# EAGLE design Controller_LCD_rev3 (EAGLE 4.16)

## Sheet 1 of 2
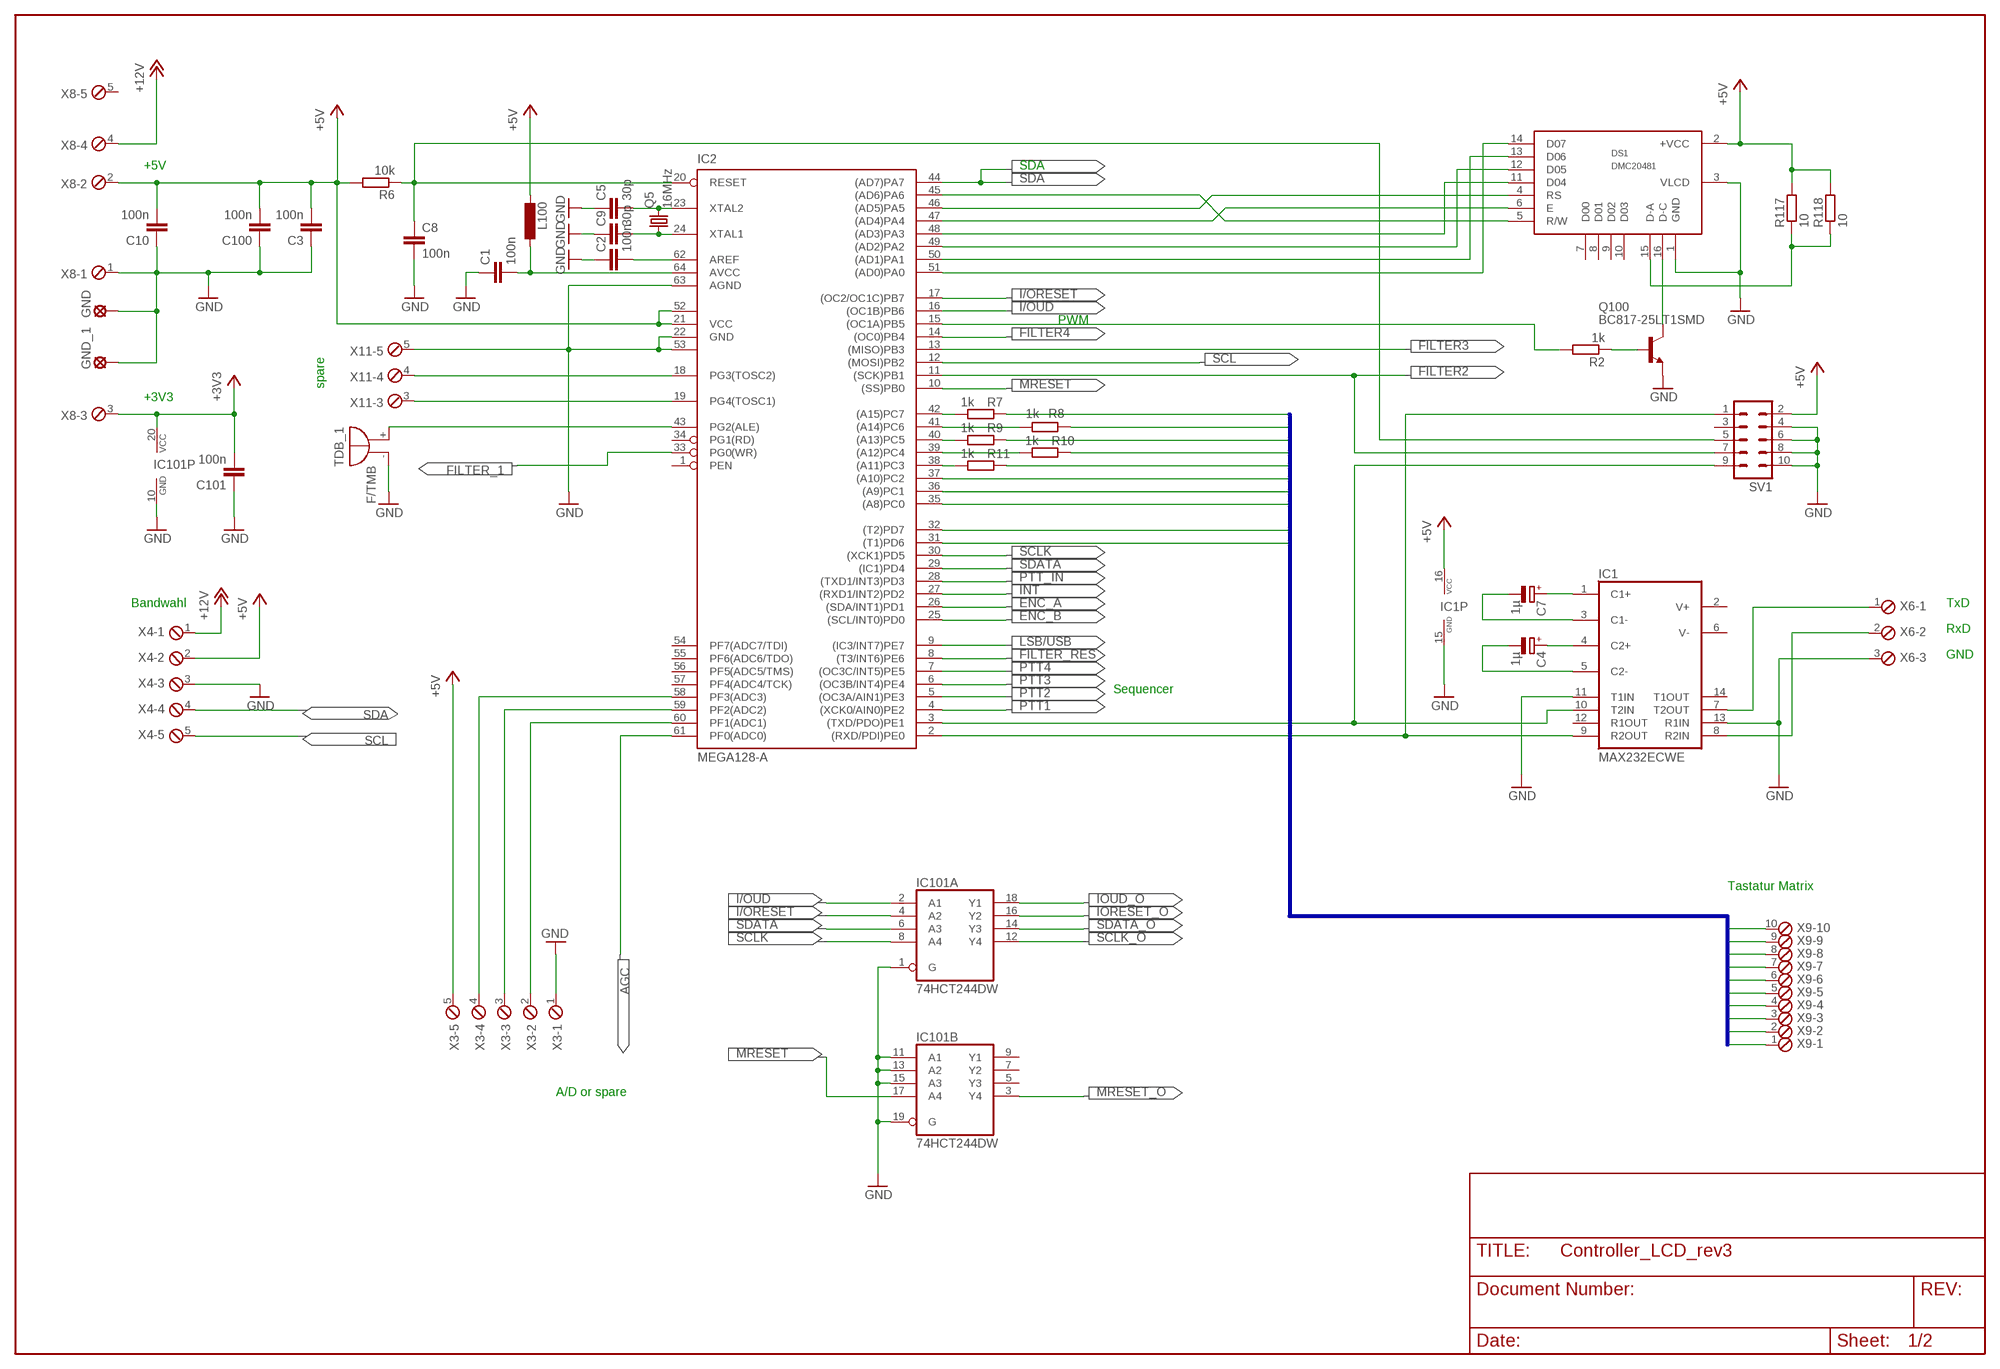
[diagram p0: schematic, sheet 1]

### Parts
C1  100n  C-EUC0805  [C0805]
C2  100n  C-EUC0805  [C0805]
C3  100n  C-EUC0805  [C0805]
C4  1µ  CPOL-EU153CLV-0505  [153CLV-0505]
C5  30p  C-EUC0805  [C0805]
C7  1µ  CPOL-EU153CLV-0505  [153CLV-0505]
C8  100n  C-EUC0805  [C0805]
C9  30p  C-EUC0805  [C0805]
C10  100n  C-EUC0805  [C0805]
C100  100n  C-EUC0805  [C0805]
C101  100n  C-EUC0805  [C0805]
DS1  DMC20481  [DM20481]
GND  LSP10  [LSP10]
GND_1  LSP10  [LSP10]
IC1  MAX232ECWE  [SO16L]
IC2  MEGA128-A  [TQFP64]
IC101  74HCT244DW  [SO20W]
L100  L-EUL1206  [L1206]
Q5  16MHz  CRYSTALHC49UP  [HC49UP]
Q100  BC817-25LT1SMD  [SOT23-BEC]
R2  1k  R-EU_M0805  [M0805]
R6  10k  R-EU_M0805  [M0805]
R7  1k  R-EU_M0805  [M0805]
R8  1k  R-EU_M0805  [M0805]
R9  1k  R-EU_M0805  [M0805]
R10  1k  R-EU_M0805  [M0805]
R11  1k  R-EU_M0805  [M0805]
R117  10  R-EU_M0805  [M0805]
R118  10  R-EU_M0805  [M0805]
SV1  ML10  [ML10]
TDB_1  F/TMB  [F/TMB]
X3  MPT5  [5POL254]
X4  MPT5  [5POL254]
X6  MPT3  [3POL254]
X8  MPT5  [5POL254]
X9  MPT10  [10POL254]
X11  MPT5  [5POL254]

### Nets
+3V3: C101.2 IC101.20(P:VCC) X8.3 ; also sheet 2
+5V: C3.2 C10.2 C100.2 DS1.2(+VCC) IC1.16(VCC) IC2.21(VCC) IC2.52(VCC1) L100.2 R6.2 R117.2 R118.2 SV1.2 X3.5 X4.2 X8.2 ; also sheet 2
+12V: X4.1 X8.4 ; also sheet 2
AGC: IC2.61(PF0(ADC0)) ; also sheet 2
COL1: IC2.37((A10)PC2) X9.5
COL2: IC2.36((A9)PC1) X9.4
COL3: IC2.35((A8)PC0) X9.3
COL4: IC2.32((T2)PD7) X9.2
COL5: IC2.31((T1)PD6) X9.1
D04: DS1.11(D04) IC2.48((AD3)PA3)
D05: DS1.12(D05) IC2.49((AD2)PA2)
D06: DS1.13(D06) IC2.50((AD1)PA1)
D07: DS1.14(D07) IC2.51((AD0)PA0)
E: DS1.6(E) IC2.47((AD4)PA4)
ENC_A: IC2.26((SDA/INT1)PD1) ; also sheet 2
ENC_B: IC2.25((SCL/INT0)PD0) ; also sheet 2
FILTER2: IC2.11((SCK)PB1) SV1.7 ; also sheet 2
FILTER3: IC2.13((MISO)PB3) ; also sheet 2
FILTER4: IC2.14((OC0)PB4) ; also sheet 2
FILTER_1: IC2.33(PG0(WR)) ; also sheet 2
FILTER_RES: IC2.8((T3/INT6)PE6) ; also sheet 2
GND: C1.1 C2.1 C3.1 C5.1 C8.2 C9.1 C10.1 C100.1 C101.1 DS1.1(GND) DS1.3(VLCD) GND.MP GND_1.MP IC1.11(T1IN) IC1.13(R1IN) IC1.15(GND) IC2.22(GND) IC2.53(GND1) IC2.63(AGND) IC101.1(A:G) IC101.10(P:GND) IC101.11(B:A1) IC101.13(B:A2) IC101.15(B:A3) IC101.19(B:G) Q100.E SV1.4 SV1.6 SV1.8 SV1.10 TDB_1.- X3.1 X4.3 X6.3 X8.1 X11.5 ; also sheet 2
I/ORESET: IC2.17((OC2/OC1C)PB7) IC101.4(A:A2)
I/OUD: IC2.16((OC1B)PB6) IC101.2(A:A1)
INT: IC2.27((RXD1/INT2)PD2) ; also sheet 2
IORESET_O: IC101.16(A:Y2) ; also sheet 2
IOUD_O: IC101.18(A:Y1) ; also sheet 2
LSB/USB: IC2.9((IC3/INT7)PE7) ; also sheet 2
MRESET: IC2.10((SS)PB0) IC101.17(B:A4)
MRESET_O: IC101.3(B:Y4) ; also sheet 2
N1: IC2.39((A12)PC4) R10.2
N2: IC2.41((A14)PC6) R8.2
N$1: C5.2 IC2.23(XTAL2) Q5.2
N$2: C9.2 IC2.24(XTAL1) Q5.1
N$8: DS1.15(D-A) R117.1 R118.1
N$9: Q100.B R2.1
N$13: IC2.15((OC1A)PB5) R2.2
N$14: IC1.9(R2OUT) IC2.2((RXD/PDI)PE0) SV1.1
N$15: IC1.10(T2IN) IC2.3((TXD/PDO)PE1) SV1.9
N$19: C7.+ IC1.1(C1+)
N$20: C7.- IC1.3(C1-)
N$21: C4.+ IC1.4(C2+)
N$22: C4.- IC1.5(C2-)
N$23: DS1.16(D-C) Q100.C
N$28: IC2.58(PF3(ADC3)) X3.4
N$29: IC2.59(PF2(ADC2)) X3.3
N$30: IC2.60(PF1(ADC1)) X3.2
N$38: IC2.38((A11)PC3) R11.2
N$39: IC2.40((A13)PC5) R9.2
N$40: IC2.42((A15)PC7) R7.2
N$79: IC2.43(PG2(ALE)) TDB_1.+
N$80: IC2.18(PG3(TOSC2)) X11.4
N$81: IC2.19(PG4(TOSC1)) X11.3
N$83: C2.2 IC2.62(AREF)
N$84: C1.2 IC2.64(AVCC) L100.1
PTT1: IC2.4((XCK0/AIN0)PE2) ; also sheet 2
PTT2: IC2.5((OC3A/AIN1)PE3) ; also sheet 2
PTT3: IC2.6((OC3B/INT4)PE4) ; also sheet 2
PTT4: IC2.7((OC3C/INT5)PE5) ; also sheet 2
PTT_IN: IC2.28((TXD1/INT3)PD3) ; also sheet 2
R/W: DS1.5(R/W) IC2.45((AD6)PA6)
RESET: C8.1 IC2.20(RESET) R6.1 SV1.5
ROW1: R7.1 X9.10
ROW2: R8.1 X9.9
ROW3: R9.1 X9.8
ROW4: R10.1 X9.7
ROW5: R11.1 X9.6
RS: DS1.4(RS) IC2.46((AD5)PA5)
RXD: IC1.8(R2IN) X6.2
SCL: IC2.12((MOSI)PB2) X4.5 ; also sheet 2
SCLK: IC2.30((XCK1)PD5) IC101.8(A:A4)
SCLK_O: IC101.12(A:Y4) ; also sheet 2
SDA: IC2.44((AD7)PA7) X4.4 ; also sheet 2
SDATA: IC2.29((IC1)PD4) IC101.6(A:A3)
SDATA_O: IC101.14(A:Y3) ; also sheet 2
TXD: IC1.7(T2OUT) X6.1
Unconnected: DS1.7(D00) DS1.8(D01) DS1.9(D02) DS1.10(D03) IC1.2(V+) IC1.6(V-) IC1.12(R1OUT) IC1.14(T1OUT) IC2.1(PEN) IC2.34(PG1(RD)) IC2.54(PF7(ADC7/TDI)) IC2.55(PF6(ADC6/TDO)) IC2.56(PF5(ADC5/TMS)) IC2.57(PF4(ADC4/TCK)) IC101.5(B:Y3) IC101.7(B:Y2) IC101.9(B:Y1) SV1.3 X8.5 X11.1 X11.2

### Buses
KEY

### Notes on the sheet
- +5V | SDA
- PWM
- spare
- +3V3
- Bandwahl | TxD
- RxD
- GND
- Sequencer
- Tastatur Matrix
- A/D or spare

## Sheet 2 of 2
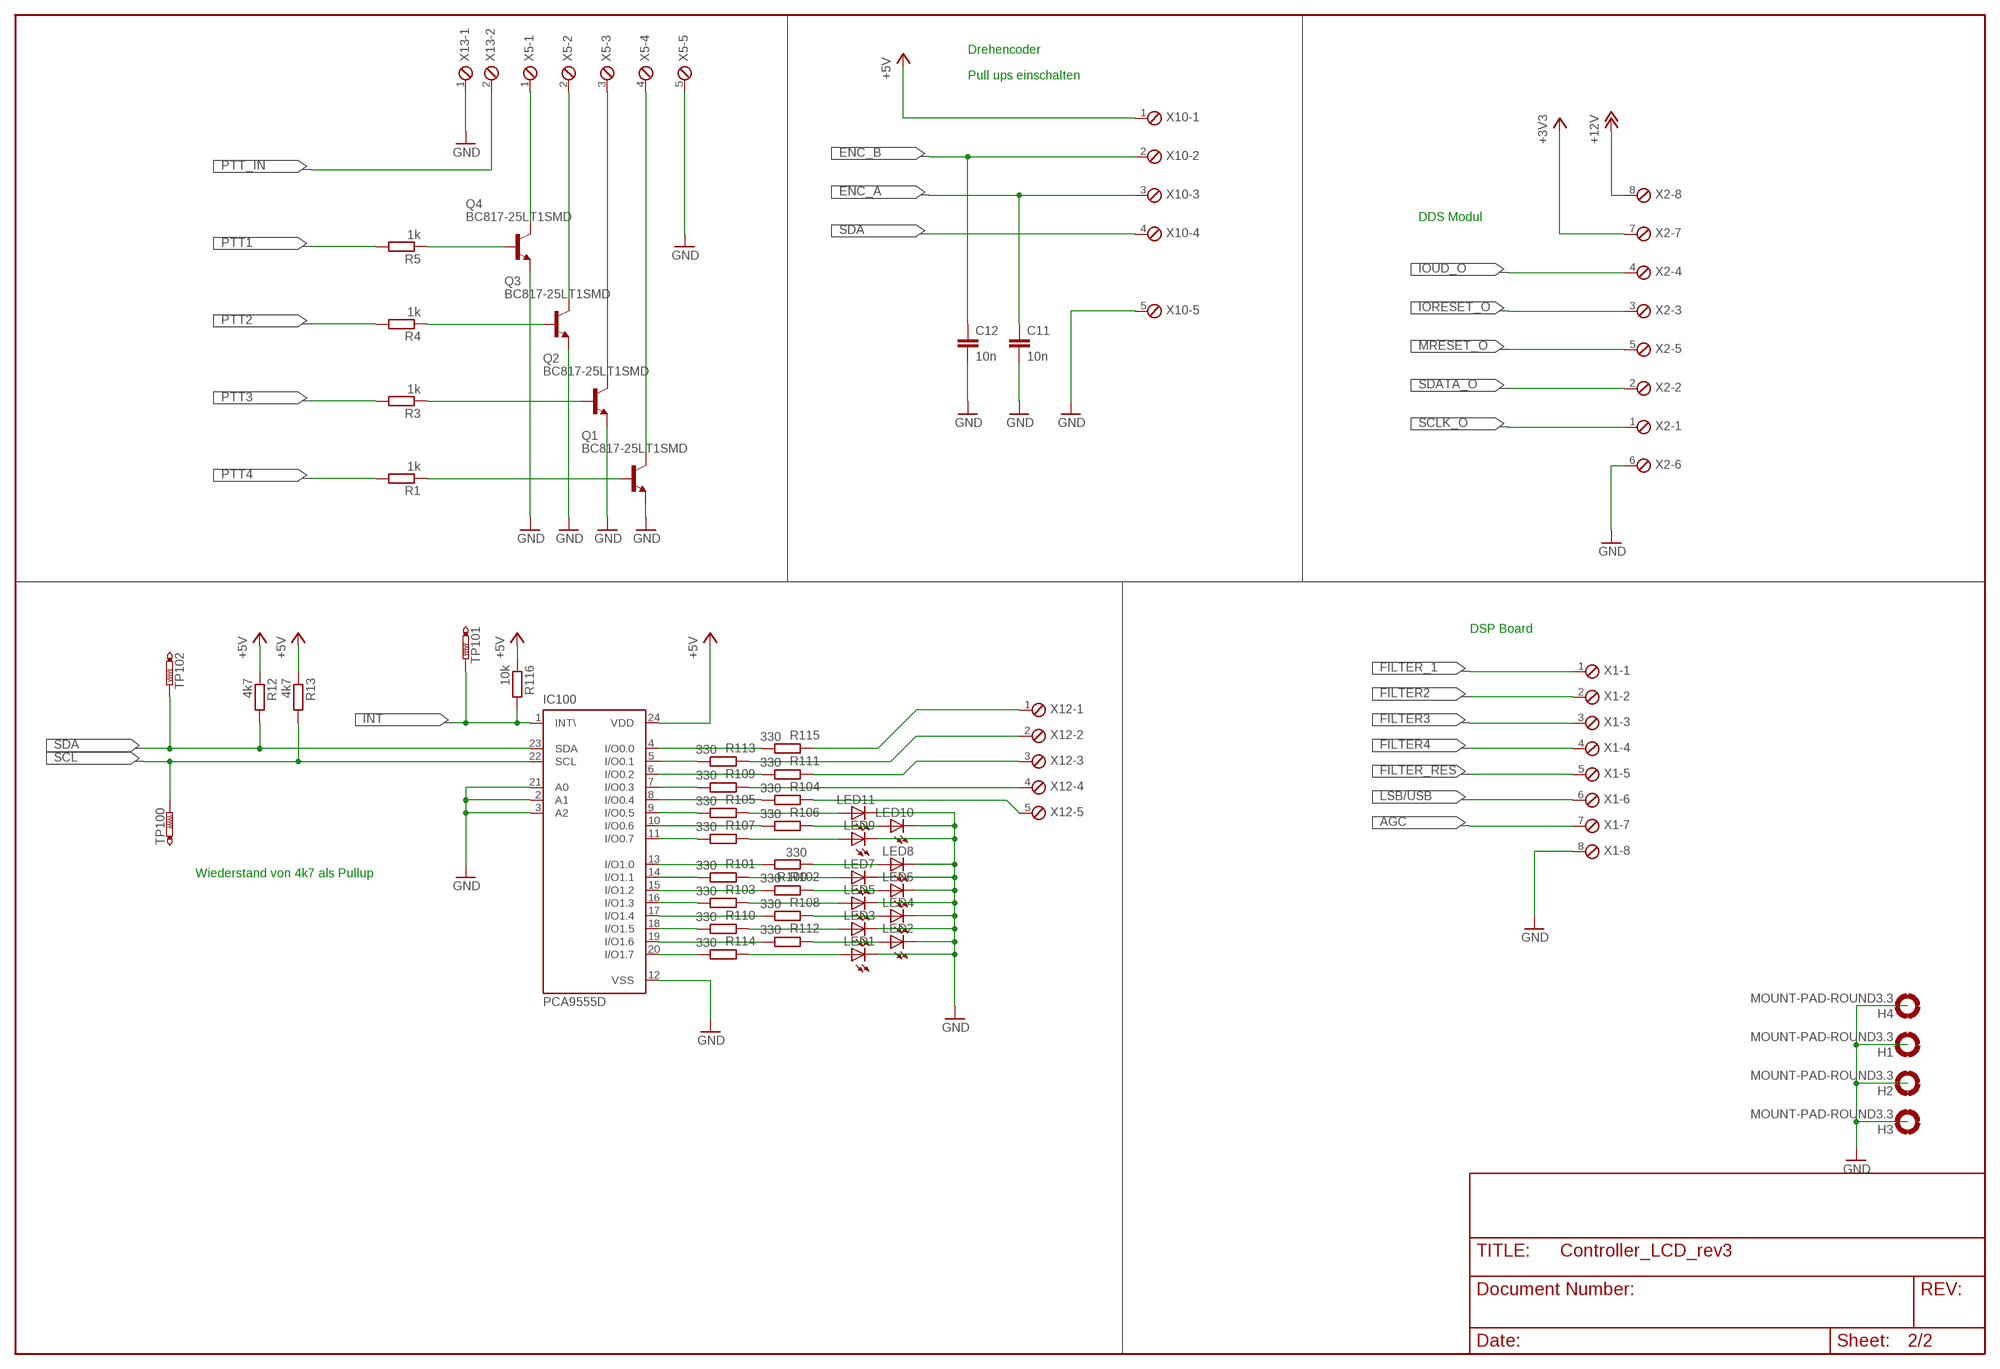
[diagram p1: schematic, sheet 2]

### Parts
C11  10n  C-EUC0805K  [C0805K]
C12  10n  C-EUC0805K  [C0805K]
H1  MOUNT-PAD-ROUND3.3  [3,3-PAD]
H2  MOUNT-PAD-ROUND3.3  [3,3-PAD]
H3  MOUNT-PAD-ROUND3.3  [3,3-PAD]
H4  MOUNT-PAD-ROUND3.3  [3,3-PAD]
IC100  PCA9555D  [SO24]
LED1  LED5MM  [LED5MM]
LED2  LED5MM  [LED5MM]
LED3  LED5MM  [LED5MM]
LED4  LED5MM  [LED5MM]
LED5  LED5MM  [LED5MM]
LED6  LED5MM  [LED5MM]
LED7  LED5MM  [LED5MM]
LED8  LED5MM  [LED5MM]
LED9  LED5MM  [LED5MM]
LED10  LED5MM  [LED5MM]
LED11  LED5MM  [LED5MM]
Q1  BC817-25LT1SMD  [SOT23-BEC]
Q2  BC817-25LT1SMD  [SOT23-BEC]
Q3  BC817-25LT1SMD  [SOT23-BEC]
Q4  BC817-25LT1SMD  [SOT23-BEC]
R1  1k  R-EU_M0805  [M0805]
R3  1k  R-EU_M0805  [M0805]
R4  1k  R-EU_M0805  [M0805]
R5  1k  R-EU_M0805  [M0805]
R12  4k7  R-EU_M0805  [M0805]
R13  4k7  R-EU_M0805  [M0805]
R100  330  R-EU_M0805  [M0805]
R101  330  R-EU_M0805  [M0805]
R102  330  R-EU_M0805  [M0805]
R103  330  R-EU_M0805  [M0805]
R104  330  R-EU_M0805  [M0805]
R105  330  R-EU_M0805  [M0805]
R106  330  R-EU_M0805  [M0805]
R107  330  R-EU_M0805  [M0805]
R108  330  R-EU_M0805  [M0805]
R109  330  R-EU_M0805  [M0805]
R110  330  R-EU_M0805  [M0805]
R111  330  R-EU_M0805  [M0805]
R112  330  R-EU_M0805  [M0805]
R113  330  R-EU_M0805  [M0805]
R114  330  R-EU_M0805  [M0805]
R115  330  R-EU_M0805  [M0805]
R116  10k  R-EU_M0805  [M0805]
TP100  PTR1B2,54  [B2,54]
TP101  PTR1B2,54  [B2,54]
TP102  PTR1B2,54  [B2,54]
X1  MPT8  [8POL254]
X2  MPT8  [8POL254]
X5  MPT5  [5POL254]
X10  MPT5  [5POL254]
X12  MPT5  [5POL254]
X13  MPT2  [2POL254]

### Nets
+3V3: X2.7 ; also sheet 1
+5V: IC100.24(VDD) R12.1 R13.1 R116.1 X10.1 ; also sheet 1
+12V: X2.8 ; also sheet 1
AGC: X1.7 ; also sheet 1
ENC_A: C11.1 X10.3 ; also sheet 1
ENC_B: C12.1 X10.2 ; also sheet 1
FILTER2: X1.2 ; also sheet 1
FILTER3: X1.3 ; also sheet 1
FILTER4: X1.4 ; also sheet 1
FILTER_1: X1.1 ; also sheet 1
FILTER_RES: X1.5 ; also sheet 1
GND: C11.2 C12.2 H1.B3,3(MOUNT) H2.B3,3(MOUNT) H3.B3,3(MOUNT) H4.B3,3(MOUNT) IC100.2(A1) IC100.3(A2) IC100.12(VSS) IC100.21(A0) LED1.K(C) LED2.K(C) LED3.K(C) LED4.K(C) LED5.K(C) LED6.K(C) LED7.K(C) LED8.K(C) LED9.K(C) LED10.K(C) LED11.K(C) Q1.E Q2.E Q3.E Q4.E X1.8 X2.6 X5.5 X10.5 X13.1 ; also sheet 1
INT: IC100.1(INT\) R116.2 TP101.PP(TP) ; also sheet 1
IORESET_O: X2.3 ; also sheet 1
IOUD_O: X2.4 ; also sheet 1
LSB/USB: X1.6 ; also sheet 1
MRESET_O: X2.5 ; also sheet 1
N$3: Q4.B R5.1
N$12: IC100.4(I/O0.0) R115.2
N$17: IC100.5(I/O0.1) R113.2
N$18: IC100.6(I/O0.2) R111.2
N$31: Q3.B R4.1
N$32: Q2.B R3.1
N$33: Q1.B R1.1
N$34: Q4.C X5.1
N$35: Q3.C X5.2
N$36: Q2.C X5.3
N$37: Q1.C X5.4
N$41: IC100.7(I/O0.3) R109.2
N$42: IC100.8(I/O0.4) R104.2
N$43: IC100.9(I/O0.5) R105.2
N$44: IC100.10(I/O0.6) R106.2
N$45: IC100.11(I/O0.7) R107.2
N$46: R115.1 X12.1
N$47: R113.1 X12.2
N$48: R109.1 X12.4
N$49: R111.1 X12.3
N$50: R104.1 X12.5
N$51: LED11.A R105.1
N$52: LED10.A R106.1
N$53: LED9.A R107.1
N$54: IC100.20(I/O1.7) R114.2
N$55: IC100.19(I/O1.6) R112.2
N$56: IC100.18(I/O1.5) R110.2
N$57: IC100.17(I/O1.4) R108.2
N$58: IC100.16(I/O1.3) R103.2
N$59: IC100.15(I/O1.2) R102.2
N$60: IC100.14(I/O1.1) R101.2
N$61: IC100.13(I/O1.0) R100.2
N$62: LED8.A R100.1
N$63: LED7.A R101.1
N$64: LED5.A R103.1
N$65: LED6.A R102.1
N$66: LED4.A R108.1
N$67: LED3.A R110.1
N$68: LED2.A R112.1
N$69: LED1.A R114.1
PTT1: R5.2 ; also sheet 1
PTT2: R4.2 ; also sheet 1
PTT3: R3.2 ; also sheet 1
PTT4: R1.2 ; also sheet 1
PTT_IN: X13.2 ; also sheet 1
SCL: IC100.22(SCL) R13.2 TP100.PP(TP) ; also sheet 1
SCLK_O: X2.1 ; also sheet 1
SDA: IC100.23(SDA) R12.2 TP102.PP(TP) X10.4 ; also sheet 1
SDATA_O: X2.2 ; also sheet 1

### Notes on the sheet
- Drehencoder
- Pull ups einschalten
- DDS Modul
- DSP Board
- Wiederstand von 4k7 als Pullup

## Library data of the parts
C1-C3 C5 C8-C12 C100 C101 = rcl:C-EU: CAPACITOR, European symbol
C4 C7 = rcl:CPOL-EU: POLARIZED CAPACITOR, European symbol
DS1 = abi-lcd:DMC20481
GND GND_1 = solpad:LSP10: SOLDER PAD
H1-H4 = holes:MOUNT-PAD-ROUND: MOUNTING PAD, round
IC1 = maxim:MAX232ECWE: RS232 TRANSEIVER
IC2 = atmel:MEGA128: MICROCONTROLLER 128 Kbytes FLASH 4 Kbytes SRAM 4 Kbytes EEPROM DUAL USART 8-channel 10 bit ADC Source: avr.lbr
IC100 = micro-philips:PCA9555: 16-bit I2C and SMBus I/O port with interrupt Source: PCA9555_5.pdf
IC101 = 74xx-eu:74*244: Octal BUFFER and LINE DRIVER, 3-state
L100 = rcl:L-EU: INDUCTOR, European symbol
LED1-LED11 = led:LED: LED
Q1-Q4 Q100 = transistor-npn:BC817*: NPN Transistor
Q5 = crystal:CRYSTAL: CRYSTAL
R1-R13 R100-R118 = rcl:R-EU_: RESISTOR, European symbol
SV1 = con-harting-ml:ML10: HARTING
TDB_1 = buzzer:F/TMB: BUZZER
TP100-TP102 = testpad:PTR1: TEST PIN
X1 X2 = con-phoenix-254:MPT8: PHOENIX CONNECTOR
X3-X5 X8 X10-X12 = con-phoenix-254:MPT5: PHOENIX CONNECTOR
X6 = con-phoenix-254:MPT3: PHOENIX CONNECTOR
X9 = con-phoenix-254:MPT10: PHOENIX CONNECTOR
X13 = con-phoenix-254:MPT2: PHOENIX CONNECTOR

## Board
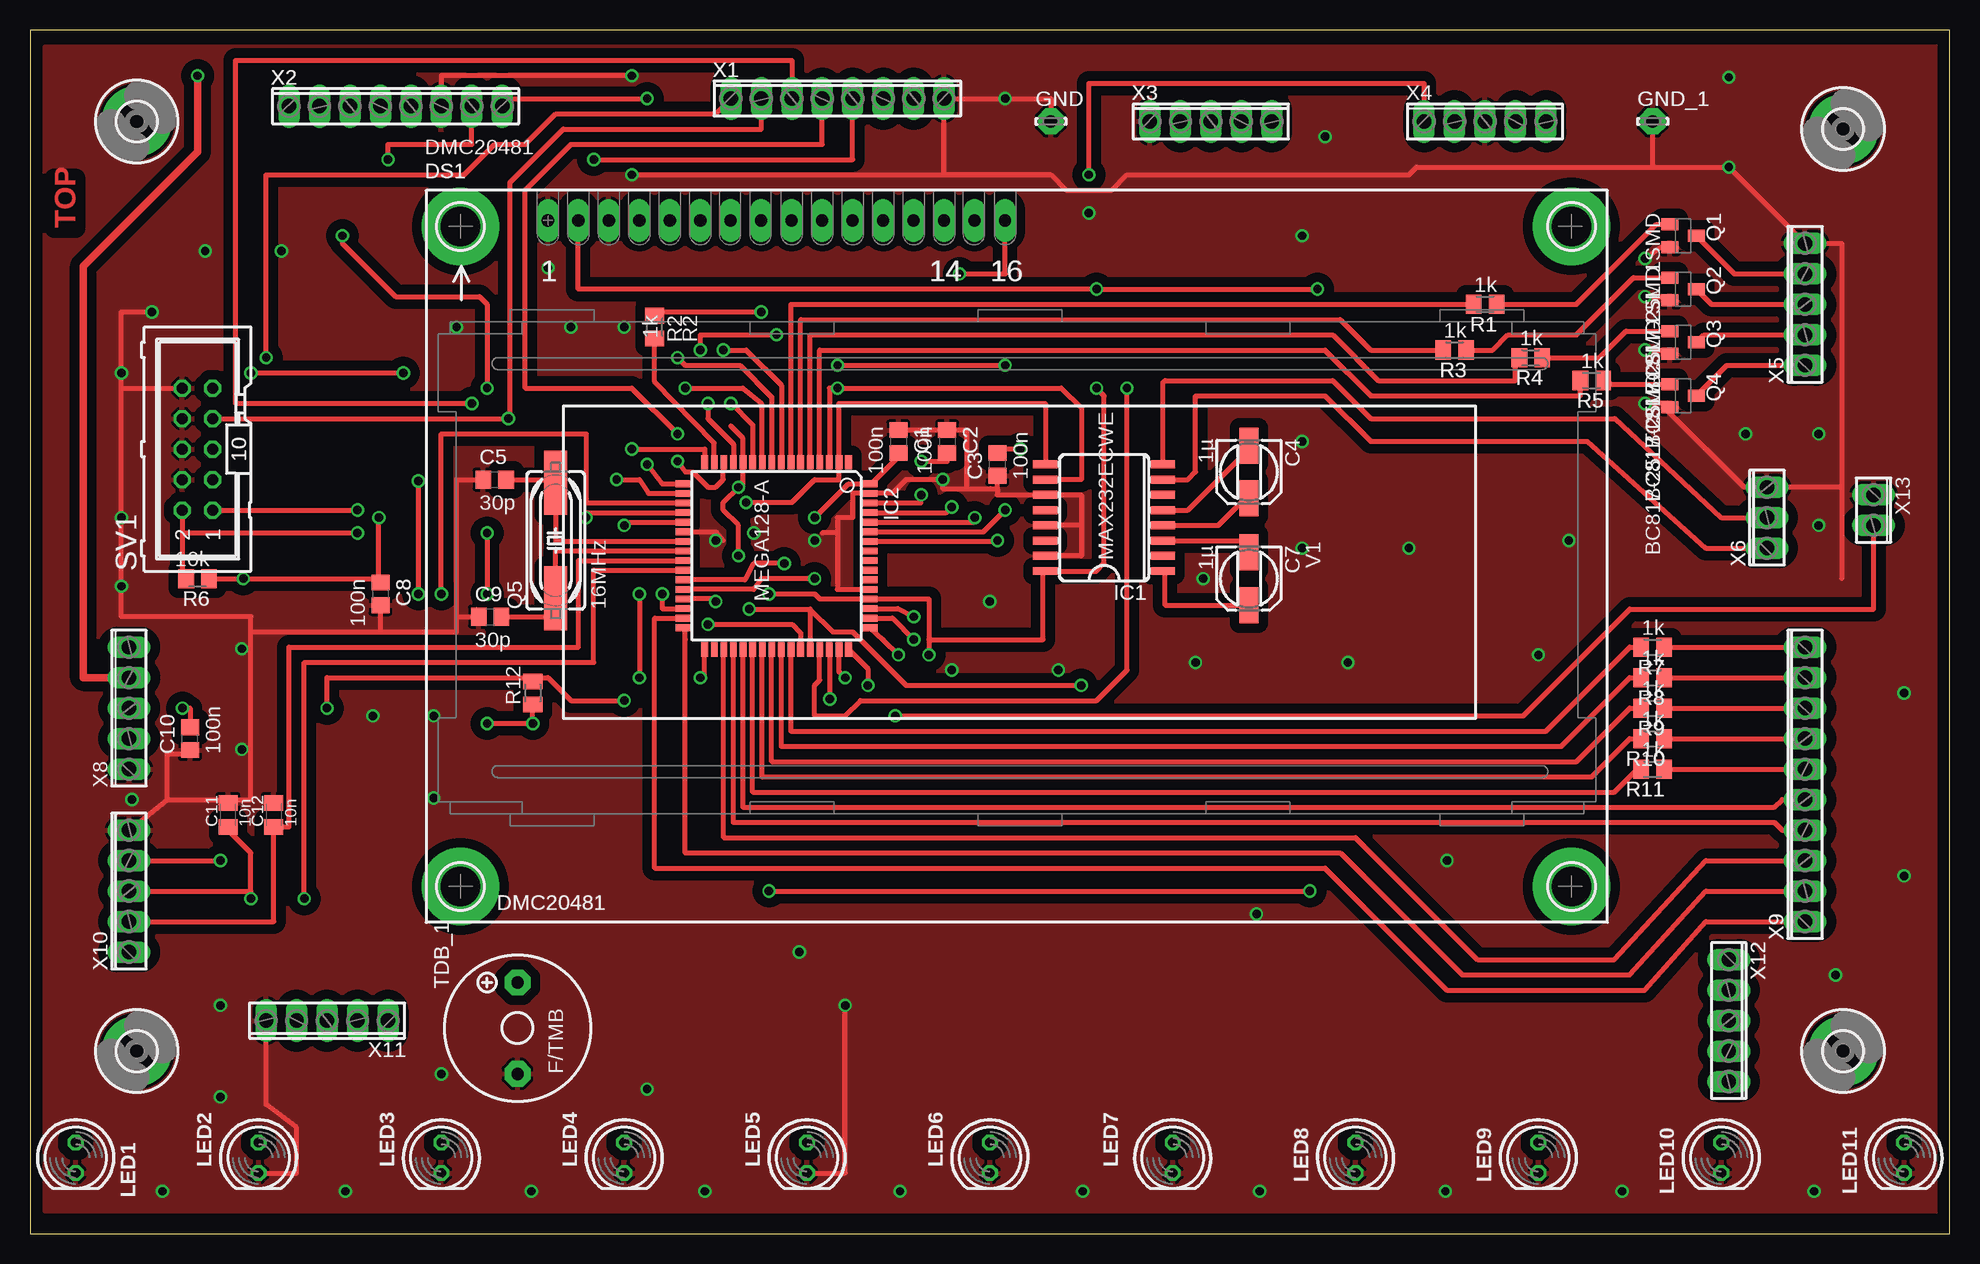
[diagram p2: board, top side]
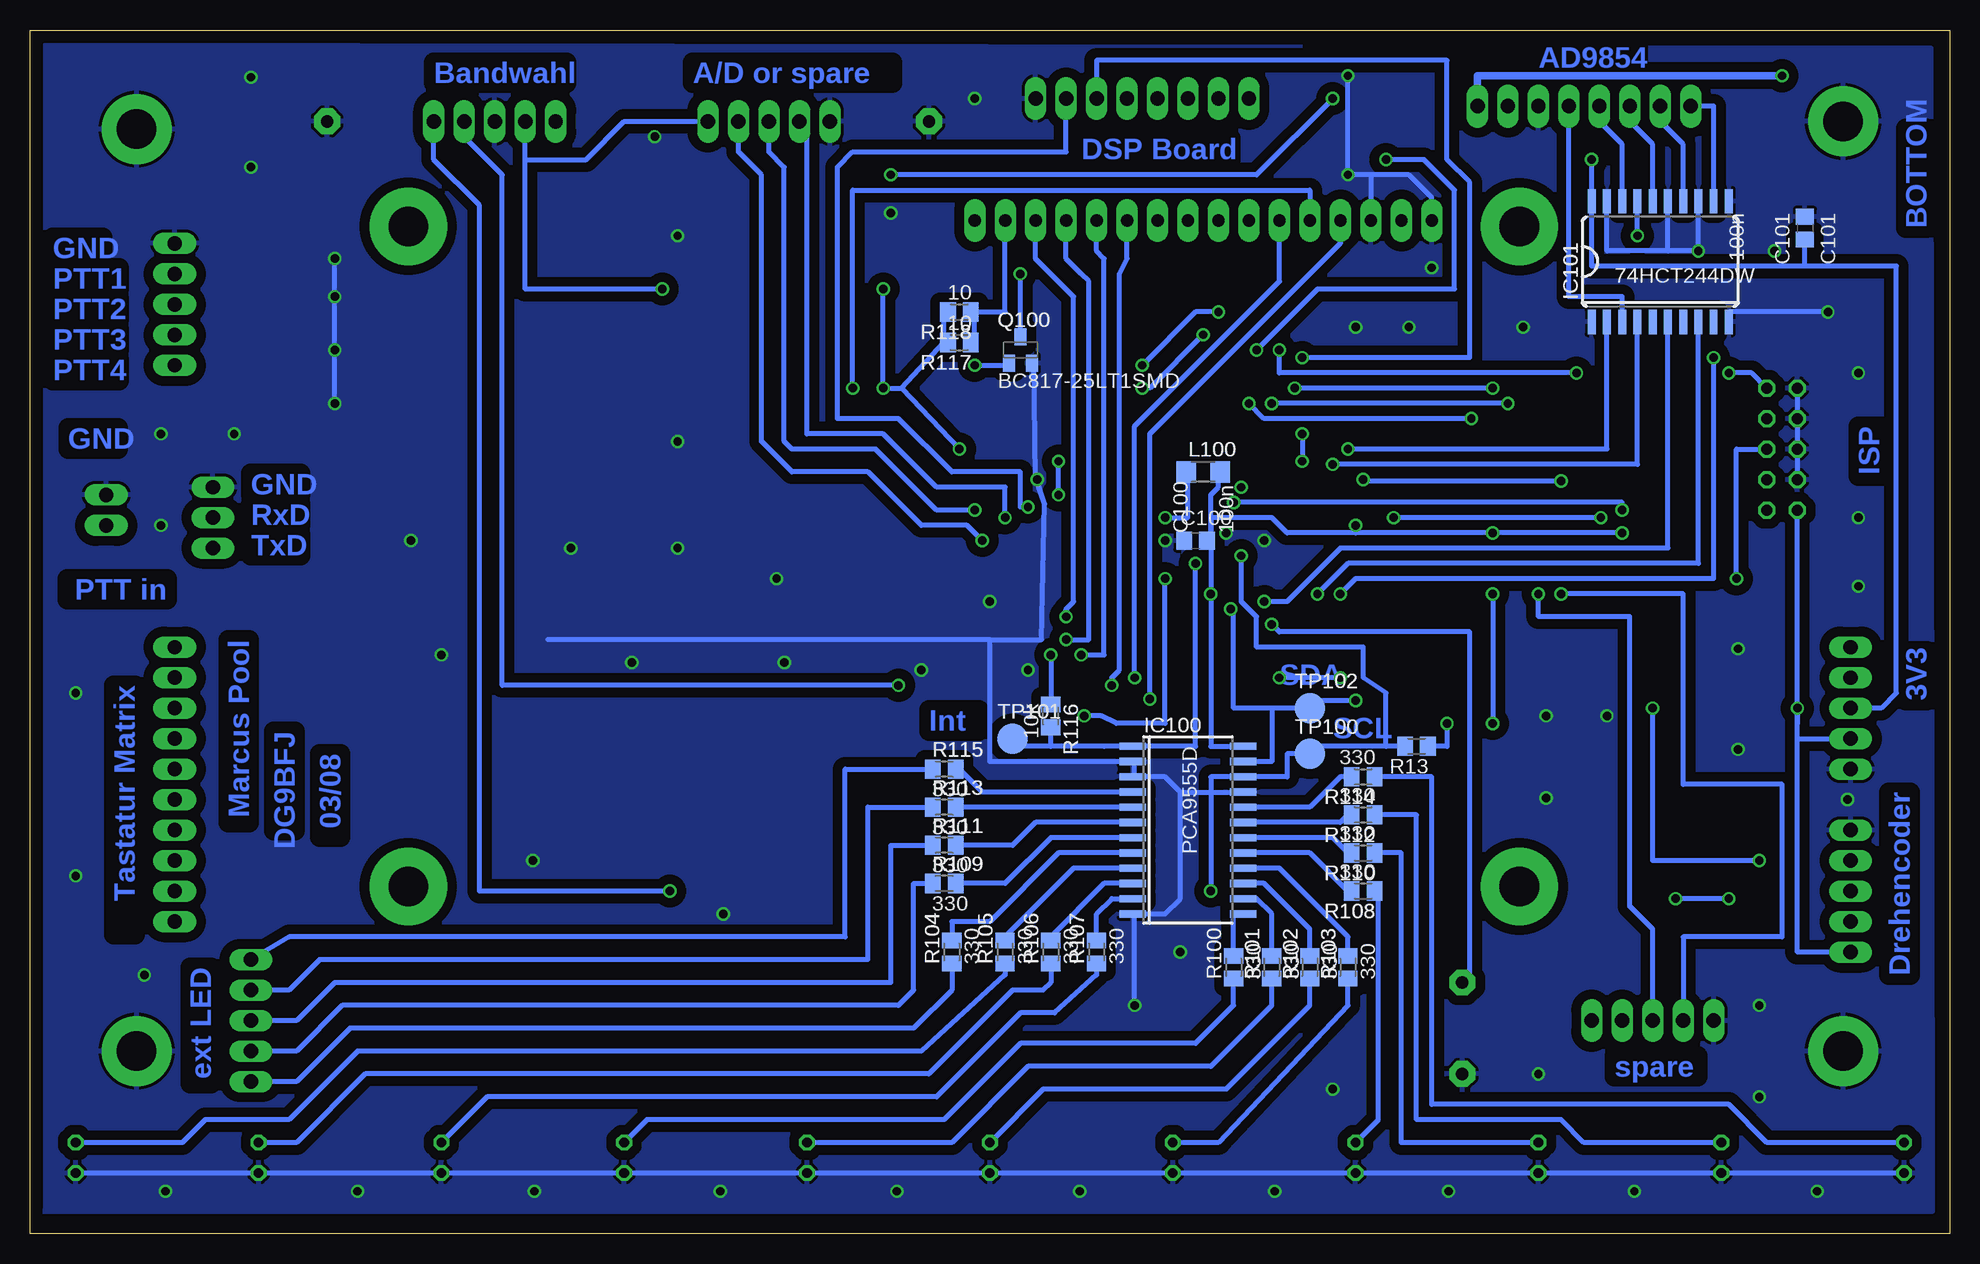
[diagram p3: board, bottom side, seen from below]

Size 160.02 x 100.33 mm. Coordinates in mm from the lower left corner, seen from the top.
Outline: 0,0 160.02,0 160.02,100.33 0,100.33 0,0
Copper layers (1*16): Top 0.035mm / dielectric 1.5mm / Bottom 0.035mm
Design rules "Bilex DRU": minimum track width 10mil, minimum drill 24mil, track to track 10mil, track to pad 10mil, pad to pad 10mil, via to via 10mil, smd to smd 10mil, copper to edge 40mil, drill to drill 8mil, minimum pad ring 10mil, minimum via ring 8mil, stop-mask expansion 4mil, vias tented up to drill 0mil, thermal gap 10mil

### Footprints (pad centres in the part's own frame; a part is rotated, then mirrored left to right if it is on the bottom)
C0805 = smd 1.3 x 1.5: 1 -0.95,0; 2 0.95,0
153CLV-0505 = smd 3 x 1.6: + 2.2,0; - -2.2,0
C0805K = smd 1.3 x 1.6: 1 -1,0; 2 1,0
DM20481 = drill 1.016 pad 1.778 long: 1 -39.383,29.21; 2 -36.843,29.21; 3 -34.303,29.21; 4 -31.763,29.21; 5 -29.223,29.21; 6 -26.683,29.21; 7 -24.143,29.21; 8 -21.603,29.21; 9 -19.063,29.21; 10 -16.523,29.21; 11 -13.983,29.21; 12 -11.443,29.21; 13 -8.903,29.21; 14 -6.363,29.21; 15 -3.823,29.21; 16 -1.283,29.21 | drill 3.3 pad 6.452: P$1 -46.672,-26.289; P$2 45.936,-26.289; P$3 45.936,28.715; P$4 -46.672,28.702
LSP10 = drill 1.016 pad 2.159 octagon: MP 0,0
3,3-PAD = drill 3.3 pad 5.842: B3,3 0,0
SO16L = smd 0.66 x 2.032: 1 -4.445,-4.902; 2 -3.175,-4.902; 3 -1.905,-4.902; 4 -0.635,-4.902; 5 0.635,-4.902; 6 1.905,-4.902; 7 3.175,-4.902; 8 4.445,-4.902; 9 4.445,4.902; 10 3.175,4.902; 11 1.905,4.902; 12 0.635,4.902; 13 -0.635,4.902; 14 -1.905,4.902; 15 -3.175,4.902; 16 -4.445,4.902
TQFP64 = smd 1.194 x 0.559: 1 -7.8,6; 2 -7.8,5.2; 3 -7.8,4.4; 4 -7.8,3.6; 5 -7.8,2.8; 6 -7.8,2; 7 -7.8,1.2; 8 -7.8,0.4; 9 -7.8,-0.4; 10 -7.8,-1.2; 11 -7.8,-2; 12 -7.8,-2.8; 13 -7.8,-3.6; 14 -7.8,-4.4; 15 -7.8,-5.2; 16 -7.8,-6; 33 7.8,-6; 34 7.8,-5.2; 35 7.8,-4.4; 36 7.8,-3.6; 37 7.8,-2.8; 38 7.8,-2; 39 7.8,-1.2; 40 7.8,-0.4; 41 7.8,0.4; 42 7.8,1.2; 43 7.8,2; 44 7.8,2.8; 45 7.8,3.6; 46 7.8,4.4; 47 7.8,5.2; 48 7.8,6 | smd 0.559 x 1.194: 17 -6,-7.8; 18 -5.2,-7.8; 19 -4.4,-7.8; 20 -3.6,-7.8; 21 -2.8,-7.8; 22 -2,-7.8; 23 -1.2,-7.8; 24 -0.4,-7.8; 25 0.4,-7.8; 26 1.2,-7.8; 27 2,-7.8; 28 2.8,-7.8; 29 3.6,-7.8; 30 4.4,-7.8; 31 5.2,-7.8; 32 6,-7.8; 49 6,7.8; 50 5.2,7.8; 51 4.4,7.8; 52 3.6,7.8; 53 2.8,7.8; 54 2,7.8; 55 1.2,7.8; 56 0.4,7.8; 57 -0.4,7.8; 58 -1.2,7.8; 59 -2,7.8; 60 -2.8,7.8; 61 -3.6,7.8; 62 -4.4,7.8; 63 -5.2,7.8; 64 -6,7.8
SO24 = smd 0.6 x 2.2: 1 -6.985,-4.6; 2 -5.715,-4.6; 3 -4.445,-4.6; 4 -3.175,-4.6; 5 -1.905,-4.6; 6 -0.635,-4.6; 7 0.635,-4.6; 8 1.905,-4.6; 9 3.175,-4.6; 10 4.445,-4.6; 11 5.715,-4.6; 12 6.985,-4.6; 13 6.985,4.6; 14 5.715,4.6; 15 4.445,4.6; 16 3.175,4.6; 17 1.905,4.6; 18 0.635,4.6; 19 -0.635,4.6; 20 -1.905,4.6; 21 -3.175,4.6; 22 -4.445,4.6; 23 -5.715,4.6; 24 -6.985,4.6
SO20W = smd 0.66 x 2.032: 1 -5.715,-5.029; 2 -4.445,-5.029; 3 -3.175,-5.029; 4 -1.905,-5.029; 5 -0.635,-5.029; 6 0.635,-5.029; 7 1.905,-5.029; 8 3.175,-5.029; 9 4.445,-5.029; 10 5.715,-5.029; 11 5.715,5.029; 12 4.445,5.029; 13 3.175,5.029; 14 1.905,5.029; 15 0.635,5.029; 16 -0.635,5.029; 17 -1.905,5.029; 18 -3.175,5.029; 19 -4.445,5.029; 20 -5.715,5.029
L1206 = smd 1.6 x 1.803: 1 -1.422,0; 2 1.422,0
LED5MM = drill 0.813 octagon: A -1.27,0; K 1.27,0
SOT23-BEC = smd 1 x 1.4: B -0.95,-1.1; C 0,1.1; E 0.95,-1.1
HC49UP = smd 5.334 x 1.93: 1 -4.826,0; 2 4.826,0
M0805 = smd 1.3 x 1.6: 1 -0.95,0; 2 0.95,0
ML10 = drill 0.914 octagon: 1 -5.08,-1.27; 2 -5.08,1.27; 3 -2.54,-1.27; 4 -2.54,1.27; 5 0,-1.27; 6 0,1.27; 7 2.54,-1.27; 8 2.54,1.27; 9 5.08,-1.27; 10 5.08,1.27
F/TMB = drill 1.016 pad 2.159 octagon: + 3.81,0; - -3.81,0
B2,54 = smd 2.54 x 2.54: PP 0,0
8POL254 = drill 1.2 long: 1 -8.89,0; 2 -6.35,0; 3 -3.81,0; 4 -1.27,0; 5 1.27,0; 6 3.81,0; 7 6.35,0; 8 8.89,0
5POL254 = drill 1.2 long: 1 -5.08,0; 2 -2.54,0; 3 0,0; 4 2.54,0; 5 5.08,0
3POL254 = drill 1.2 long: 1 -2.54,0; 2 0,0; 3 2.54,0
10POL254 = drill 1.2 long: 1 -11.43,0; 2 -8.89,0; 3 -6.35,0; 4 -3.81,0; 5 -1.27,0; 6 1.27,0; 7 3.81,0; 8 6.35,0; 9 8.89,0; 10 11.43,0
2POL254 = drill 1.2 long: 1 -1.27,0; 2 1.27,0

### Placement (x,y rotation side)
C1  72.39,66.04 270 top
C2  76.45,66.04 270 top
C3  80.64,64.14 90 top
C4  101.6,63.5 270 top
C5  38.73,62.87 0 top
C7  101.6,54.61 270 top
C8  29.21,53.34 270 top
C9  38.35,51.44 0 top
C10  13.34,41.27 90 top
C11  16.51,34.92 90 top
C12  20.32,34.92 90 top
C100  62.87,57.78 0 bottom
C101  12.06,83.82 270 bottom
DS1  82.55,55.24 0 top
GND  85.09,92.71 0 top
GND_1  135.25,92.71 0 top
H1  8.89,92.71 0 top
H2  151.13,92.08 0 top
H3  151.13,15.24 0 top
H4  8.89,15.24 0 top
IC1  89.53,59.69 90 top
IC2  62.23,56.52 270 top
IC100  63.5,33.66 270 bottom
IC101  24.13,81.03 0 bottom
L100  62.23,63.5 0 bottom
LED1  3.81,6.35 270 top
LED2  19.05,6.35 270 top
LED3  34.29,6.35 270 top
LED4  49.53,6.35 270 top
LED5  64.77,6.35 270 top
LED6  80.01,6.35 270 top
LED7  95.25,6.35 270 top
LED8  110.49,6.35 270 top
LED9  125.73,6.35 270 top
LED10  140.97,6.35 270 top
LED11  156.21,6.35 270 top
Q1  137.79,83.19 270 top
Q2  137.79,78.74 270 top
Q3  137.79,74.3 270 top
Q4  137.79,69.85 270 top
Q5  43.81,57.78 90 top
Q100  77.47,73.66 0 bottom
R1  121.28,77.47 180 top
R2  52.07,75.56 270 top
R3  118.75,73.66 180 top
R4  125.09,73.03 180 top
R5  130.18,71.12 180 top
R6  13.97,54.61 180 top
R7  135.25,48.9 180 top
R8  135.25,46.35 180 top
R9  135.25,43.81 180 top
R10  135.25,41.27 180 top
R11  135.25,38.73 180 top
R12  41.91,45.09 90 top
R13  44.45,40.64 180 bottom
R100  59.69,22.23 90 bottom
R101  56.52,22.23 90 bottom
R102  53.34,22.23 90 bottom
R103  50.16,22.23 90 bottom
R104  83.19,23.5 90 bottom
R105  78.74,23.5 90 bottom
R106  74.93,23.5 90 bottom
R107  71.12,23.5 90 bottom
R108  48.9,28.57 180 bottom
R109  83.82,29.21 0 bottom
R110  48.9,31.75 180 bottom
R111  83.82,32.38 0 bottom
R112  48.9,34.92 180 bottom
R113  83.82,35.56 0 bottom
R114  48.9,38.1 180 bottom
R115  83.82,38.73 0 bottom
R116  74.93,43.18 270 bottom
R117  82.55,74.3 180 bottom
R118  82.55,76.83 180 bottom
SV1  13.97,65.41 90 top
TDB_1  40.64,17.14 90 top
TP100  53.34,40.01 0 bottom
TP101  78.11,41.27 0 bottom
TP102  53.34,43.81 0 bottom
X1  67.31,94.61 0 top
X2  30.48,93.98 0 top
X3  98.42,92.71 0 top
X4  121.28,92.71 0 top
X5  147.96,77.47 90 top
X6  144.78,59.69 90 top
X8  8.26,43.81 90 top
X9  147.96,37.47 90 top
X10  8.26,28.57 90 top
X11  24.77,17.78 180 top
X12  141.6,17.78 270 top
X13  153.67,60.33 270 top

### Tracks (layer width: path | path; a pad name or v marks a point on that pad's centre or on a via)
+3V3  (via drill 0.7)
  Top 0.406: v29.84,89.53 29.84,90.81 36.83,90.81 X2.7
  Bottom 0.406: 12.06,80.64 C101.2 | v29.84,89.53 IC101.20 29.84,80.64 12.06,80.64 | X8.3 5.71,43.81 4.45,45.09 4.45,80.64 12.06,80.64
+5V  (via drill 0.7)
  Top 0.406: v61.59,53.34 65.41,53.34 65.83,52.91 IC2.52 74.93,52.91 74.93,49.53 | R6.2 12.7,54.61 12.7,58.42 | 84.45,55.24 IC1.16 | 74.93,49.53 84.45,49.53 84.45,55.24 | 84.45,55.24 88.9,55.24 89.53,55.88 89.53,69.85 v88.9,70.48 | SV1.2 12.7,58.42 | 12.7,58.42 v27.3,58.42 | DS1.2 45.71,78.74 v88.9,78.74 v107.31,78.74 | v82.55,65.41 80.64,65.41 C3.2 80.64,64.77 | C10.2 13.02,42.55 13.34,42.55 13.34,43.81 v12.7,43.81 | 74.93,49.53 v74.93,48.26 | R12.1 v41.91,42.55 v38.1,42.55 | v38.1,58.42 v38.1,53.34 | IC2.21 49.53,59.31 v49.53,59.05
  Bottom 0.406: 61.59,58.42 61.59,57.78 | 61.59,57.78 v61.59,53.34 61.59,40.64 IC100.24 | DS1.2 | R118.2 83.82,76.83 83.82,74.3 | 83.82,74.3 R117.2 | 87.38,70.48 v88.9,70.48 v88.9,78.74 | 87.38,70.48 83.82,74.3 | 12.7,41.27 12.7,23.5 X10.1 | 12.7,41.27 v12.7,43.81 | v27.3,58.42 v38.1,58.42 49.53,58.42 | 87.38,70.48 v82.55,65.41 | L100.2 60.96,63.5 60.96,62.23 61.59,61.59 61.59,58.42 | v12.7,43.81 12.7,42.55 | v74.93,48.26 R116.1 | 12.7,41.27 X8.2 | v12.7,43.81 SV1.2 | v107.31,78.74 118.75,78.74 118.75,89.53 | 118.75,89.53 X4.2 | R13.1 41.91,40.64 v41.91,42.55 | v38.1,53.34 v38.1,42.55 | 49.53,58.42 55.24,58.42 56.52,59.69 61.59,59.69 61.59,58.42 | 49.53,58.42 v49.53,59.05 | 61.59,57.78 C100.2 | X3.5 110.49,92.71 113.67,89.53 118.75,89.53
+12V  (via drill 0.7)
  Top 0.406: X2.8 39.37,94.61 v51.44,94.61 | v88.27,88.27 88.27,95.89 116.2,95.89 X4.1
  Top 0.61: v13.97,96.52 13.97,90.17 4.45,80.64 4.45,46.35 X8.4
  Bottom 0.406: v51.44,94.61 57.78,88.27 v88.27,88.27
  Bottom 0.61: v13.97,96.52 39.37,96.52 X2.8
AGC  (via drill 0.7)
  Top 0.406: IC2.61 76.37,60.12 v76.83,60.58
  Bottom 0.406: X1.7 73.66,90.17 91.44,90.17 92.71,88.9 92.71,67.94 87.63,67.94 83.19,63.5 77.47,63.5 77.47,60.58 v76.83,60.58
COL1
  Top 0.406: IC2.37 59.43,35.56 145.41,35.56 146.05,36.2 X9.5
COL2
  Top 0.406: IC2.36 58.63,34.29 145.41,34.29 146.05,33.66 X9.4
COL3
  Top 0.406: IC2.35 57.83,33.02 110.49,33.02 120.65,22.86 132.08,22.86 139.7,31.11 X9.3
COL4
  Top 0.406: X9.2 139.7,28.57 133.35,21.59 119.38,21.59 109.22,31.75 54.61,31.75 54.61,49.53 54.61,50.52 IC2.32
COL5
  Top 0.406: IC2.31 52.07,51.31 52.07,30.48 107.95,30.48 118.11,20.32 134.62,20.32 139.7,26.04 X9.1
D04  (via drill 0.7 pad 1.02)
  Top 0.406: IC2.48 69.85,47.09 v69.85,45.72
  Bottom 0.406: DS1.11 68.58,81.28 69.22,80.01 69.22,46.99 69.85,46.35 v69.85,45.72
D05  (via drill 0.7)
  Top 0.406: v72.39,48.26 71.12,49.53 IC2.49
  Bottom 0.406: DS1.12 71.12,81.92 70.48,81.28 70.48,48.26 v72.39,48.26
D06  (via drill 0.7)
  Top 0.406: IC2.50 71.88,51.31 v73.66,49.53
  Bottom 0.406: DS1.13 73.66,81.28 72.4,80.02 71.75,79.39 71.75,49.53 v73.66,49.53
D07  (via drill 0.7)
  Top 0.406: IC2.51 72.34,52.12 v73.66,51.44
  Bottom 0.406: DS1.14 76.19,81.27 73.03,78.11 73.03,52.7 73.66,52.07 v73.66,51.44
E  (via drill 0.7)
  Top 0.406: IC2.47 67.43,46.87 v67.94,46.35
  Bottom 0.406: DS1.6 55.87,79.39 67.94,67.31 v67.94,46.35
ENC_A  (via drill 0.7)
  Top 0.406: IC2.26 46.99,55.31 46.99,47.62 22.86,47.62 v22.86,27.94 | 18.41,28.57 18.41,31.75 16.51,33.66 C11.1 | 18.41,28.57 v18.41,27.94 | X10.3 18.41,28.57
  Bottom 0.406: v18.41,27.94 v22.86,27.94
ENC_B
  Top 0.406: IC2.25 45.72,56.12 45.72,48.9 21.59,48.9 21.59,33.92 C12.1 20.32,26.04 X10.2
FILTER2  (via drill 0.7)
  Top 0.406: IC2.11 60.23,67.41 v58.42,69.22 | X1.2 60.96,92.08 44.45,92.08 40.01,87.63 40.01,67.94 SV1.7 v39.88,67.94
  Bottom 0.406: v39.88,67.94 57.15,67.94 v58.42,69.22
FILTER3  (via drill 0.7)
  Top 0.406: IC2.13 58.63,65.83 56.52,67.94 v56.52,69.22 | v36.83,69.22 17.14,69.22 17.14,97.79 63.5,97.79 X1.3
  Bottom 0.406: v36.83,69.22 v56.52,69.22
FILTER4  (via drill 0.7)
  Top 0.406: X1.4 66.04,90.81 45.09,90.81 41.27,87 41.27,70.48 50.16,70.48 v53.98,66.67 | IC2.14 57.78,62.87 57.2,62.27 57.15,62.27 57.15,62.23 56.52,62.23 55.24,63.5 54.61,63.5 v53.98,64.39
  Bottom 0.406: v53.98,66.67 v53.98,64.39
FILTER_1  (via drill 0.7)
  Top 0.406: X1.1 57.15,93.34 43.81,93.34 41.27,90.81 38.73,90.81 36.2,88.27 19.68,88.27 v19.68,73.03 | IC2.33 56.23,46.35 v55.88,46.35 | v50.8,53.34 v50.8,46.35
  Bottom 0.406: v19.68,73.03 19.68,54.61 49.53,54.61 v50.8,53.34 | v50.8,46.35 v55.88,46.35
FILTER_RES  (via drill 0.7)
  Top 0.406: IC2.8 62.63,70.72 59.69,73.66 v57.78,73.66 | v46.99,89.53 68.58,89.53 X1.5
  Bottom 0.406: v57.78,73.66 52.7,78.74 41.27,78.74 41.27,87 43.81,89.53 v46.99,89.53
GND  (via drill 0.7)
  Top 0.406: 35.56,50.16 35.56,62.87 C5.1 | IC2.53 67.31,53.72 67.31,58.42 | 57.78,57.78 57.15,58.52 IC2.22 | 35.56,50.16 35.56,51.44 C9.1 | 29.21,50.16 35.56,50.16 | 29.21,50.16 C8.2 | 67.31,58.42 67.31,59.69 68.58,59.69 68.58,61.72 IC2.63 71.88,61.72 73.03,62.87 v76.07,62.87 76.07,62.1 78.11,62.1 | 151,62.23 151,54.61 | 151,62.23 X6.3 | Q1.E 136.38,82.55 v134.62,81.28 | 136.53,69.22 136.53,69.07 Q4.E 136.53,68.9 136.53,69.22 | 136.53,69.22 v134.62,69.22 | Q3.E 136.38,73.66 v134.62,73.66 | Q2.E 136.38,78.11 v134.62,78.11 | 151,62.23 142.88,62.23 136.53,68.58 136.53,69.22 | LED5.K 67.94,5.08 v67.94,19.05 | 78.11,62.1 80.08,62.1 80.64,62.1 | IC1.15 87.63,56.52 87.63,59.05 | 84.45,59.05 IC1.13 87.63,59.05 | 87.63,59.05 87.63,61.59 IC1.11 80.64,61.59 80.64,62.1 | 7.62,70.48 SV1.10 | 7.62,70.48 7.62,51.44 18.41,51.44 18.41,50.16 | 7.62,70.48 7.62,76.83 v10.16,76.83 | 151,62.23 151,82.55 X5.5 v141.6,88.9 135.25,88.9 | 11.43,36.2 18.41,36.2 18.41,50.16 | X10.5 11.43,36.2 | 85.09,88.27 76.2,88.27 X1.8 85.09,94.61 GND.MP | v50.16,88.27 85.09,88.27 | X2.6 34.29,96.52 v50.16,96.52 | 11.43,36.2 11.43,40.01 13.34,40.01 C10.1 | 80.64,62.1 C3.1 | 67.31,58.42 66.04,58.42 | 85.09,88.27 86.36,87 90.17,87 91.44,88.27 114.94,88.27 115.57,88.9 135.25,88.9 | X11.5 19.68,10.79 22.23,8.89 22.23,5.08 LED2.K | 135.25,88.9 GND_1.MP | 18.41,50.16 29.21,50.16 | C2.1 78.11,66.99 78.11,62.1 | C2.1 C1.1 | C2.1 76.33,67.31
  Bottom 0.406: SV1.10 SV1.8 SV1.6 SV1.4 | 75.44,60.83 v76.07,62.87 | 75.44,60.83 76.2,62.99 76.33,72.56 Q100.E | DS1.1 43.18,86.36 45.09,88.27 48.26,88.27 | DS1.3 48.26,88.27 | 48.26,88.27 v50.16,88.27 v50.16,96.52 | v134.62,81.28 v134.62,78.11 v134.62,73.66 v134.62,69.22 | 67.94,38.1 67.94,39.22 IC100.2 80.01,39.37 80.01,49.53 | 64.14,36.83 IC100.21 | 67.94,38.1 IC100.3 | 64.14,36.83 65.41,38.1 67.94,38.1 | 67.94,26.67 65.41,26.67 64.14,27.94 64.14,36.83 | LED1.K LED2.K LED3.K LED4.K LED5.K LED6.K LED7.K LED8.K LED9.K LED10.K LED11.K | 67.94,26.67 IC100.12 | v67.94,19.05 67.94,26.67 | 80.01,49.53 116.84,49.53 | 75.44,60.83 75.69,49.53 80.01,49.53 | v20.95,81.92 28.57,81.92 IC101.19 | IC101.15 23.5,81.92 v20.95,81.92 | IC101.10 18.41,76.83 v10.16,76.83 | v20.95,81.92 IC101.13
  other vias: 33.66,43.18 28.57,43.18 34.29,13.34 51.44,12.06 15.88,19.05 15.88,11.43 7.62,53.98 7.62,59.69 7.62,71.75 43.18,80.52 45.09,75.56 49.53,75.56 81.28,94.61 88.27,85.09 107.95,91.44 106.05,83.19 106.05,66.04 106.05,57.15 97.16,47.62 109.86,47.62 125.73,48.26 143,66.67 149.1,66.67 149.1,59.05 141.6,96.39 156.21,45.09 156.21,29.84 150.5,21.59 102.23,26.67 118.11,31.11 76.83,46.99 85.72,46.99 64.14,23.5 17.65,48.77 17.65,40.39 8.51,36.2 33.66,36.32 148.72,3.56 132.72,3.56 117.98,3.56 102.49,3.56 87.76,3.56 72.52,3.56 56.26,3.56 41.78,3.56 26.29,3.56 11.05,3.56 35.56,75.56 14.61,81.92 80.01,52.7 97.79,54.61 114.94,57.15 128.27,57.78 65.41,57.78 57.15,57.78 60.33,58.42
  pour Top (isolate 0.813): 159,98.93 159,1.91 1.27,1.91 1.27,98.93
  pour Bottom (isolate 0.813): 159,1.91 1.4,1.91 1.52,98.81 158.75,99.06 158.75,1.91
I/ORESET  (via drill 0.7)
  Top 0.406: IC2.17 52.7,62.52 v51.44,64.14
  Bottom 0.406: v51.44,64.14 26.04,64.14 IC101.4
I/OUD  (via drill 0.7)
  Top 0.406: IC2.16 56.23,65.41 v50.16,65.41
  Bottom 0.406: v50.16,65.41 31.5,65.41 29.08,65.41 28.57,65.41 IC101.2
INT  (via drill 0.7)
  Top 0.406: v62.87,55.88 60.33,55.88 59.59,54.52 IC2.27
  Bottom 0.406: 70.48,40.64 74.93,40.64 R116.2 | v62.87,55.88 62.87,40.64 IC100.1 70.48,40.64 | 70.48,40.64 77.47,40.64 77.47,41.27 TP101.PP
IORESET_O
  Bottom 0.406: X2.3 26.67,92.71 24.77,90.81 IC101.16
IOUD_O
  Bottom 0.406: IC101.18 27.3,90.81 29.21,92.71 X2.4
LSB/USB  (via drill 0.7)
  Top 0.406: IC2.9 61.83,69.74 59.18,72.39 54.61,72.39 v53.98,73.03
  Bottom 0.406: v53.98,73.03 40.01,73.03 40.01,87.63 41.91,89.53 41.91,97.79 71.12,97.79 X1.6
MRESET  (via drill 0.7)
  Top 0.406: IC2.10 60.96,64.31 60.96,69.22 59.44,70.48 v54.61,70.48 | v38.1,70.48 38.1,77.47 37.47,78.11 30.48,78.11 26.04,82.55 v26.04,83.19
  Bottom 0.406: v38.1,70.48 v54.61,70.48 | 26.04,86.36 IC101.17 v26.04,83.19
MRESET_O
  Bottom 0.406: IC101.3 27.3,78.11 31.75,78.11 X2.5
N1
  Top 0.406: IC2.39 61.03,38.1 130.18,38.1 133.35,41.27 R10.2
N2
  Top 0.406: IC2.41 62.63,40.64 127.64,40.64 133.35,46.35 R8.2
N$1
  Top 0.406: IC2.23 43.81,57.72 Q5.2 43.81,62.87 C5.2
N$2
  Top 0.406: IC2.24 43.81,56.91 Q5.1 43.81,51.44 C9.2
N$3
  Top 0.406: R5.1 131.44,71.12 131.76,70.8 Q4.B
N$8
  Bottom 0.406: R117.1 81.28,74.3 81.28,76.83 | 81.28,76.83 R118.1 | DS1.15 78.74,76.83 81.28,76.83
N$9  (via drill 0.7)
  Top 0.406: v67.31,72.39 v81.28,72.39 | R2.1 52.07,76.83 v60.96,76.83
  Bottom 0.406: v81.28,72.39 78.49,72.39 78.49,72.14 78.36,72.31 Q100.B | v60.96,76.83 62.87,76.83 v67.31,72.39
N$12
  Bottom 0.406: R115.2 82.55,38.73 80.64,36.83 IC100.4
N$13
  Top 0.406: IC2.15 57.03,65.92 52.07,71 R2.2
N$14  (via drill 0.7)
  Top 0.406: IC1.9 84.63,69.22 67.43,69.22 IC2.2 67.43,62.87 65.41,62.87 63.5,60.96 v59.69,60.96 | SV1.1 v27.3,60.33
  Bottom 0.406: v27.3,60.33 27.3,60.96 v59.69,60.96
N$15  (via drill 0.7 pad 1.02)
  Top 0.406: IC2.3 66.63,70.48 v67.31,70.48 85.98,70.48 87.63,68.83 87.63,62.87 IC1.10 | v18.41,71.75 v31.11,71.75 | v62.23,74.93 55.88,74.93 v55.88,73.66
  Bottom 0.406: v18.41,71.75 16.51,71.75 SV1.9 | v62.23,74.93 66.67,70.48 v67.31,70.48 | v55.88,73.66 55.88,71.75 v31.11,71.75
N$17
  Bottom 0.406: IC100.5 78.74,35.56 | 78.74,35.56 82.55,35.56 | 78.74,35.56 R113.2
N$18
  Bottom 0.406: IC100.6 76.2,34.29 78.11,32.38 R111.2
N$19
  Top 0.406: IC1.1 94.61,55.24 94.61,52.41 C7.+
N$20
  Top 0.406: IC1.3 101.6,57.78 C7.-
N$21
  Top 0.406: C4.+ 101.6,61.59 99.06,59.05 IC1.4
N$22
  Top 0.406: C4.- 101.6,65.41 96.52,60.33 IC1.5
N$23  (via drill 0.7)
  Top 0.406: DS1.16 81.28,80.01 v77.47,80.01
  Bottom 0.406: Q100.C v77.47,80.01
N$28  (via drill 0.7)
  Top 0.406: IC2.58 80.64,57.72 v80.64,57.78
  Bottom 0.406: X3.4 100.97,90.17 99.06,88.27 99.06,66.04 96.52,63.5 90.17,63.5 85.72,59.05 81.92,59.05 v80.64,57.78
N$29  (via drill 0.7)
  Top 0.406: IC2.59 79.47,58.52 v81.28,60.33
  Bottom 0.406: v81.28,60.33 84.45,60.33 89.53,65.41 96.52,65.41 97.16,66.04 97.16,88.9 98.42,90.17 X3.3
N$30  (via drill 0.7)
  Top 0.406: IC2.60 78.74,59.31 v78.74,59.69
  Bottom 0.406: X3.2 95.25,92.08 95.25,66.67 88.9,66.67 84.45,62.23 78.74,62.23 v78.74,59.69
N$31
  Top 0.406: R4.1 130.81,73.03 133.03,75.25 Q3.B
N$32
  Top 0.406: R3.1 121.92,73.66 123.19,74.93 128.91,74.93 133.66,79.69 Q2.B
N$33
  Top 0.406: R1.1 128.91,77.47 135.57,84.14 Q1.B
N$34
  Top 0.406: Q4.C 141.44,72.39 X5.1
N$35
  Top 0.406: Q3.C 139.53,74.93 X5.2
N$36
  Top 0.406: Q2.C 140.16,77.47 X5.3
N$37
  Top 0.406: Q1.C 142.07,80.01 X5.4
N$38
  Top 0.406: IC2.38 60.23,36.83 132.08,36.83 133.99,38.73 R11.2
N$39
  Top 0.406: IC2.40 61.83,39.37 128.91,39.37 133.35,43.81 R9.2
N$40
  Top 0.406: IC2.42 63.43,41.91 126.36,41.91 133.35,48.9 R7.2 134.62,48.9
N$41
  Bottom 0.406: IC100.7 74.93,33.02 78.74,29.21 R109.2 83.19,29.21
N$42
  Bottom 0.406: R104.2 83.19,26.04 80.01,26.04 74.3,31.75 IC100.8
N$43
  Bottom 0.406: R105.2 78.74,24.77 73.03,30.48 IC100.9
N$44
  Bottom 0.406: IC100.10 70.48,29.21 74.93,24.77 R106.2
N$45
  Bottom 0.406: IC100.11 69.85,27.94 71.12,26.67 R107.2
N$46
  Bottom 0.406: X12.1 138.43,24.77 92.08,24.77 92.08,38.73 R115.1
N$47
  Bottom 0.406: X12.2 138.43,20.32 135.89,22.86 90.17,22.86 90.17,35.56 R113.1
N$48
  Bottom 0.406: X12.4 137.79,15.24 133.99,19.05 87.63,19.05 86.36,20.32 86.36,29.21 R109.1
N$49
  Bottom 0.406: X12.3 137.79,17.78 134.62,20.95 88.27,20.95 88.27,32.38 R111.1
N$50
  Bottom 0.406: X12.5 137.79,12.7 133.35,17.14 86.36,17.14 83.19,20.32 R104.1
N$51
  Bottom 0.406: LED11.A 147.32,7.62 145.41,9.53 138.43,9.53 132.72,15.24 85.72,15.24 78.74,21.59 R105.1
N$52
  Bottom 0.406: LED10.A 137.79,7.62 132.08,13.34 85.09,13.34 78.11,20.32 75.56,20.32 74.93,20.95 R106.1
N$53
  Bottom 0.406: LED9.A 121.92,11.43 84.45,11.43 77.47,18.41 74.61,18.41 71.12,21.59 R107.1
N$54
  Bottom 0.406: IC100.20 53.34,35.56 50.8,38.1 R114.2
N$55
  Bottom 0.406: R112.2 50.16,34.92 50.8,34.29 IC100.19
N$56
  Bottom 0.406: R110.2 50.16,31.75 51.44,33.02 IC100.18
N$57
  Bottom 0.406: R108.2 50.16,28.57 53.34,31.75 IC100.17
N$58
  Bottom 0.406: R103.2 50.16,24.77 55.88,30.48 IC100.16
N$59
  Bottom 0.406: R102.2 53.34,25.4 57.15,29.21 IC100.15
N$60
  Bottom 0.406: R101.2 56.52,26.67 57.78,27.94 IC100.14
N$61
  Bottom 0.406: IC100.13 59.69,26.67 R100.2
N$62
  Bottom 0.406: R100.1 59.69,19.05 62.87,15.88 77.47,15.88 83.82,9.53 108.58,9.53 LED8.A
N$63
  Bottom 0.406: R101.1 56.52,19.05 61.59,13.97 76.83,13.97 83.19,7.62 LED7.A
N$64
  Bottom 0.406: R103.1 50.16,19.05 60.96,7.62 LED5.A
N$65
  Bottom 0.406: R102.1 53.34,19.05 60.33,12.06 75.56,12.06 LED6.A
N$66
  Bottom 0.406: R108.1 47.62,28.25 47.62,9.53 LED4.A
N$67
  Bottom 0.406: R110.1 45.72,31.75 45.72,7.62 LED3.A
N$68
  Bottom 0.406: R112.1 44.45,34.92 44.45,9.53 32.38,9.53 30.48,7.62 LED2.A
N$69
  Bottom 0.406: R114.1 43.18,38.1 43.18,10.79 18.41,10.79 15.24,7.62 LED1.A
N$79  (via drill 0.7)
  Top 0.406: v56.52,50.8 63.5,50.8 64.23,50.07 IC2.43
  Bottom 0.406: TDB_1.+ 40.01,21.59 40.01,50.16 55.88,50.16 v56.52,50.8
N$80  (via drill 0.7)
  Top 0.406: IC2.18 51.55,61.72 50.8,62.87 v48.9,62.87 | v32.38,53.34 v32.38,62.74
  Bottom 0.406: v32.38,62.74 48.77,62.74 48.77,62.87 v48.9,62.87 | v32.38,53.34 22.23,53.34 22.23,37.47 13.97,37.47 13.97,24.77 22.23,24.77 X11.4
N$81  (via drill 0.7)
  Top 0.406: IC2.19 46.35,60.91 46.35,66.67 34.29,66.67 v34.29,53.34
  Bottom 0.406: X11.3 24.77,25.4 26.67,27.3 26.67,51.44 34.29,51.44 v34.29,53.34
N$83  (via drill 0.7)
  Top 0.406: C2.2 76.45,64.39 v74.3,64.39 | IC2.62 74.25,60.91 v74.3,61.59
  Bottom 0.406: v74.3,61.59 v74.3,64.39
N$84  (via drill 0.7)
  Top 0.406: v65.41,59.69 68.23,62.52 IC2.64 70.14,62.52 72.39,64.77 C1.2
  Bottom 0.406: 63.5,60.33 63.5,63.35 arc-90 L100.1 | v65.41,59.69 63.5,59.69 63.5,60.33 | 63.5,60.33 63.5,61.27
PTT1
  Top 0.406: IC2.4 65.83,73.66 107.95,73.66 111.76,69.85 129.22,69.85 R5.2 129.22,71.44
PTT2
  Top 0.406: IC2.5 65.03,74.93 108.58,74.93 112.39,71.12 123.83,71.12 123.83,73.03 R4.2
PTT3
  Top 0.406: IC2.6 64.23,76.2 109.22,76.2 111.76,73.66 R3.2
PTT4
  Top 0.406: IC2.7 63.43,77.47 R1.2 120.65,77.47
PTT_IN  (via drill 0.7)
  Top 0.406: v72.14,43.18 124.46,43.18 133.35,52.07 153.67,52.07 X13.2 | v65.41,54.61 60.96,54.61 60.33,53.72 IC2.28
  Bottom 0.406: v72.14,43.18 70.74,43.18 69.47,42.55 65.41,42.55 v65.41,54.61
R/W  (via drill 0.7)
  Top 0.406: IC2.45 65.83,46.15 65.41,45.72 65.41,43.18 67.94,43.18 69.22,44.45 88.9,44.45 91.44,46.99 v91.44,70.48
  Bottom 0.406: DS1.5 53.34,87 91.44,87 v91.44,70.48
RESET  (via drill 0.7)
  Top 0.406: IC2.20 46.35,60.12 v46.35,59.69 | C8.1 29.53,54.61 29.08,54.61 | R6.1 v17.78,54.61 29.08,54.61 | 29.08,54.61 v29.08,59.69
  Bottom 0.406: v29.08,59.69 v46.35,59.69 | v17.78,54.61 17.78,65.41 SV1.5
ROW1
  Top 0.406: R7.1 X9.10
ROW2
  Top 0.406: R8.1 X9.9
ROW3
  Top 0.406: R9.1 X9.8
ROW4
  Top 0.406: R10.1 X9.7
ROW5
  Top 0.406: R11.1 X9.6
RS  (via drill 0.7)
  Top 0.406: IC2.46 66.63,48.85 66.67,48.9 v66.67,44.58
  Bottom 0.406: DS1.4 50.79,82.56 66.67,66.67 v66.67,44.58
RXD
  Top 0.406: X6.2 140.97,59.69 132.1,67.96 | 132.08,67.94 132.1,67.96 | IC1.8 94.44,70.94 94.61,71.12 108.58,71.12 111.76,67.94 132.08,67.94 | 132.08,67.94 132.1,67.96
SCL  (via drill 0.7, 0.7 pad 1.02)
  Top 0.406: v61.59,28.57 v106.68,28.57 | 58.42,67.31 59.43,66.3 IC2.12 59.43,62.23 v59.05,62.23 57.78,60.96 57.78,60.33 59.05,59.05 v59.05,56.52
  Bottom 0.406: 59.05,38.1 IC100.22 55.24,38.1 | R13.2 46.99,40.64 | 55.24,38.1 55.24,40.01 TP100.PP 53.34,40.64 46.99,40.64 | 55.24,38.1 61.59,38.1 v61.59,28.57 | v106.68,28.57 122.56,28.57 122.56,85.72 126.36,89.53 X4.5 | 46.99,40.64 46.99,45.09 48.9,46.35 48.9,48.9 57.78,48.9 57.78,51.44 59.05,52.7 v59.05,56.52
SCLK  (via drill 0.7)
  Top 0.406: IC2.30 52.7,52.12 v52.7,53.34
  Bottom 0.406: v52.7,53.34 50.16,55.88 20.95,55.88 IC101.8
SCLK_O
  Bottom 0.406: IC101.12 19.68,93.98 X2.1
SDA  (via drill 0.7, 0.7 pad 1.02)
  Top 0.406: 65.03,52.07 IC2.44 | v59.94,52.07 65.03,52.07 | 41.91,46.35 24.77,46.35 v24.77,43.81 | X10.4 v15.88,31.11 | 41.91,46.35 R12.2 | 41.91,46.35 43.18,46.35 45.09,44.45 v49.53,44.45 | 65.03,52.07 66.94,50.16 68.58,50.16 73.03,45.72 v87.63,45.72
  Bottom 0.406: IC100.23 56.52,39.37 56.52,43.81 | 53.34,44.45 TP102.PP | 53.34,44.45 53.98,43.81 56.52,43.81 | v59.94,52.07 59.69,52.07 59.69,43.81 56.52,43.81 | v15.88,31.11 24.77,31.11 v24.77,43.81 | v49.53,44.45 53.34,44.45 | v87.63,45.72 120.65,45.72 120.65,88.27 123.83,91.44 X4.4
SDATA  (via drill 0.7)
  Top 0.406: IC2.29 57.15,52.91 v57.15,52.7
  Bottom 0.406: v57.15,52.7 55.24,52.7 50.8,57.15 23.5,57.15 IC101.6
SDATA_O
  Bottom 0.406: IC101.14 22.23,90.81 24.13,92.71 X2.2
TXD
  Top 0.406: X6.1 139.7,57.15 129.79,66.04 111.76,66.04 107.95,69.85 97.16,69.85 97.16,63.5 96.52,62.87 IC1.7

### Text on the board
Top: TOP
Bottom: AD9854 | A/D or spare | Bandwahl | DSP Board | BOTTOM | GND | PTT1 | PTT2 | PTT3 | PTT4 | ISP | GND | GND | RxD | TxD | PTT in | Marcus Pool | SDA | Tastatur Matrix | 3V3 | Int | DG9BFJ | SCL | 03/08 | Drehencoder | ext LED | spare
tNames: X2 | X1 | GND | X3 | GND_1 | LSP10 | LSP10 | DMC20481 | DS1 | BC817-25LT1SMD | Q1 | BC817-25LT1SMD | Q2 | 1k | 1 | 14 | 16 | 1k | R2 | 1k | R1 | BC817-25LT1SMD | Q3 | 1k | R3 | 1k | R4 | BC817-25LT1SMD | Q4 | X5 | R5 | 100n | C1 | 100n | C2 | 1µ | C4 | 10 | C5 | MEGA128-A | C3 | 100n | IC2 | 30p | 2 | 1 | 10k | 1µ | C7 | MAX232ECWE | X6 | SV1 | 100n | C8 | V1 | R6 | IC1 | C9 | Q5 | 16MHz | 1k | 30p | 1k | R7 | 1k | R8 | 1k | R9 | 1k | C10 | 100n | R10 | R11 | C11 | 10n | C12 | 10n | DMC20481 | X9 | X12 | X10 | TDB_1 | X11 | F/TMB
bNames: C101 | 100n | 74HCT244DW | 10 | IC101 | 10 | Q100 | R118 | R117 | BC817-25LT1SMD | L100 | 100n | C100 | TP102 | R116 | 10k | TP101 | PTR1B2,54 | TP100 | IC100 | PCA9555D | 330 | PTR1B2,54 | R115 | PTR1B2,54 | 330 | R114 | R113 | 330 | 330 | R112 | 330 | R111 | 330 | R110 | 330 | R109 | R108 | 330 | 330 | R107 | 330 | R106 | 330 | R105 | 330 | R104 | 330 | 330 | R103 | 330 | R102 | 330 | R101 | R100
